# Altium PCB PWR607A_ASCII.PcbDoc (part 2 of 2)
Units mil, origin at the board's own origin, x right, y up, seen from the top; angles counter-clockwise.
Board outline 5200 x 2850 mil, 4 copper layers (Top Layer, MidLayer1, MidLayer2, Bottom Layer), stack 61.6 mil thick; 153 components, 65 nets, 324 pads, 227 vias.
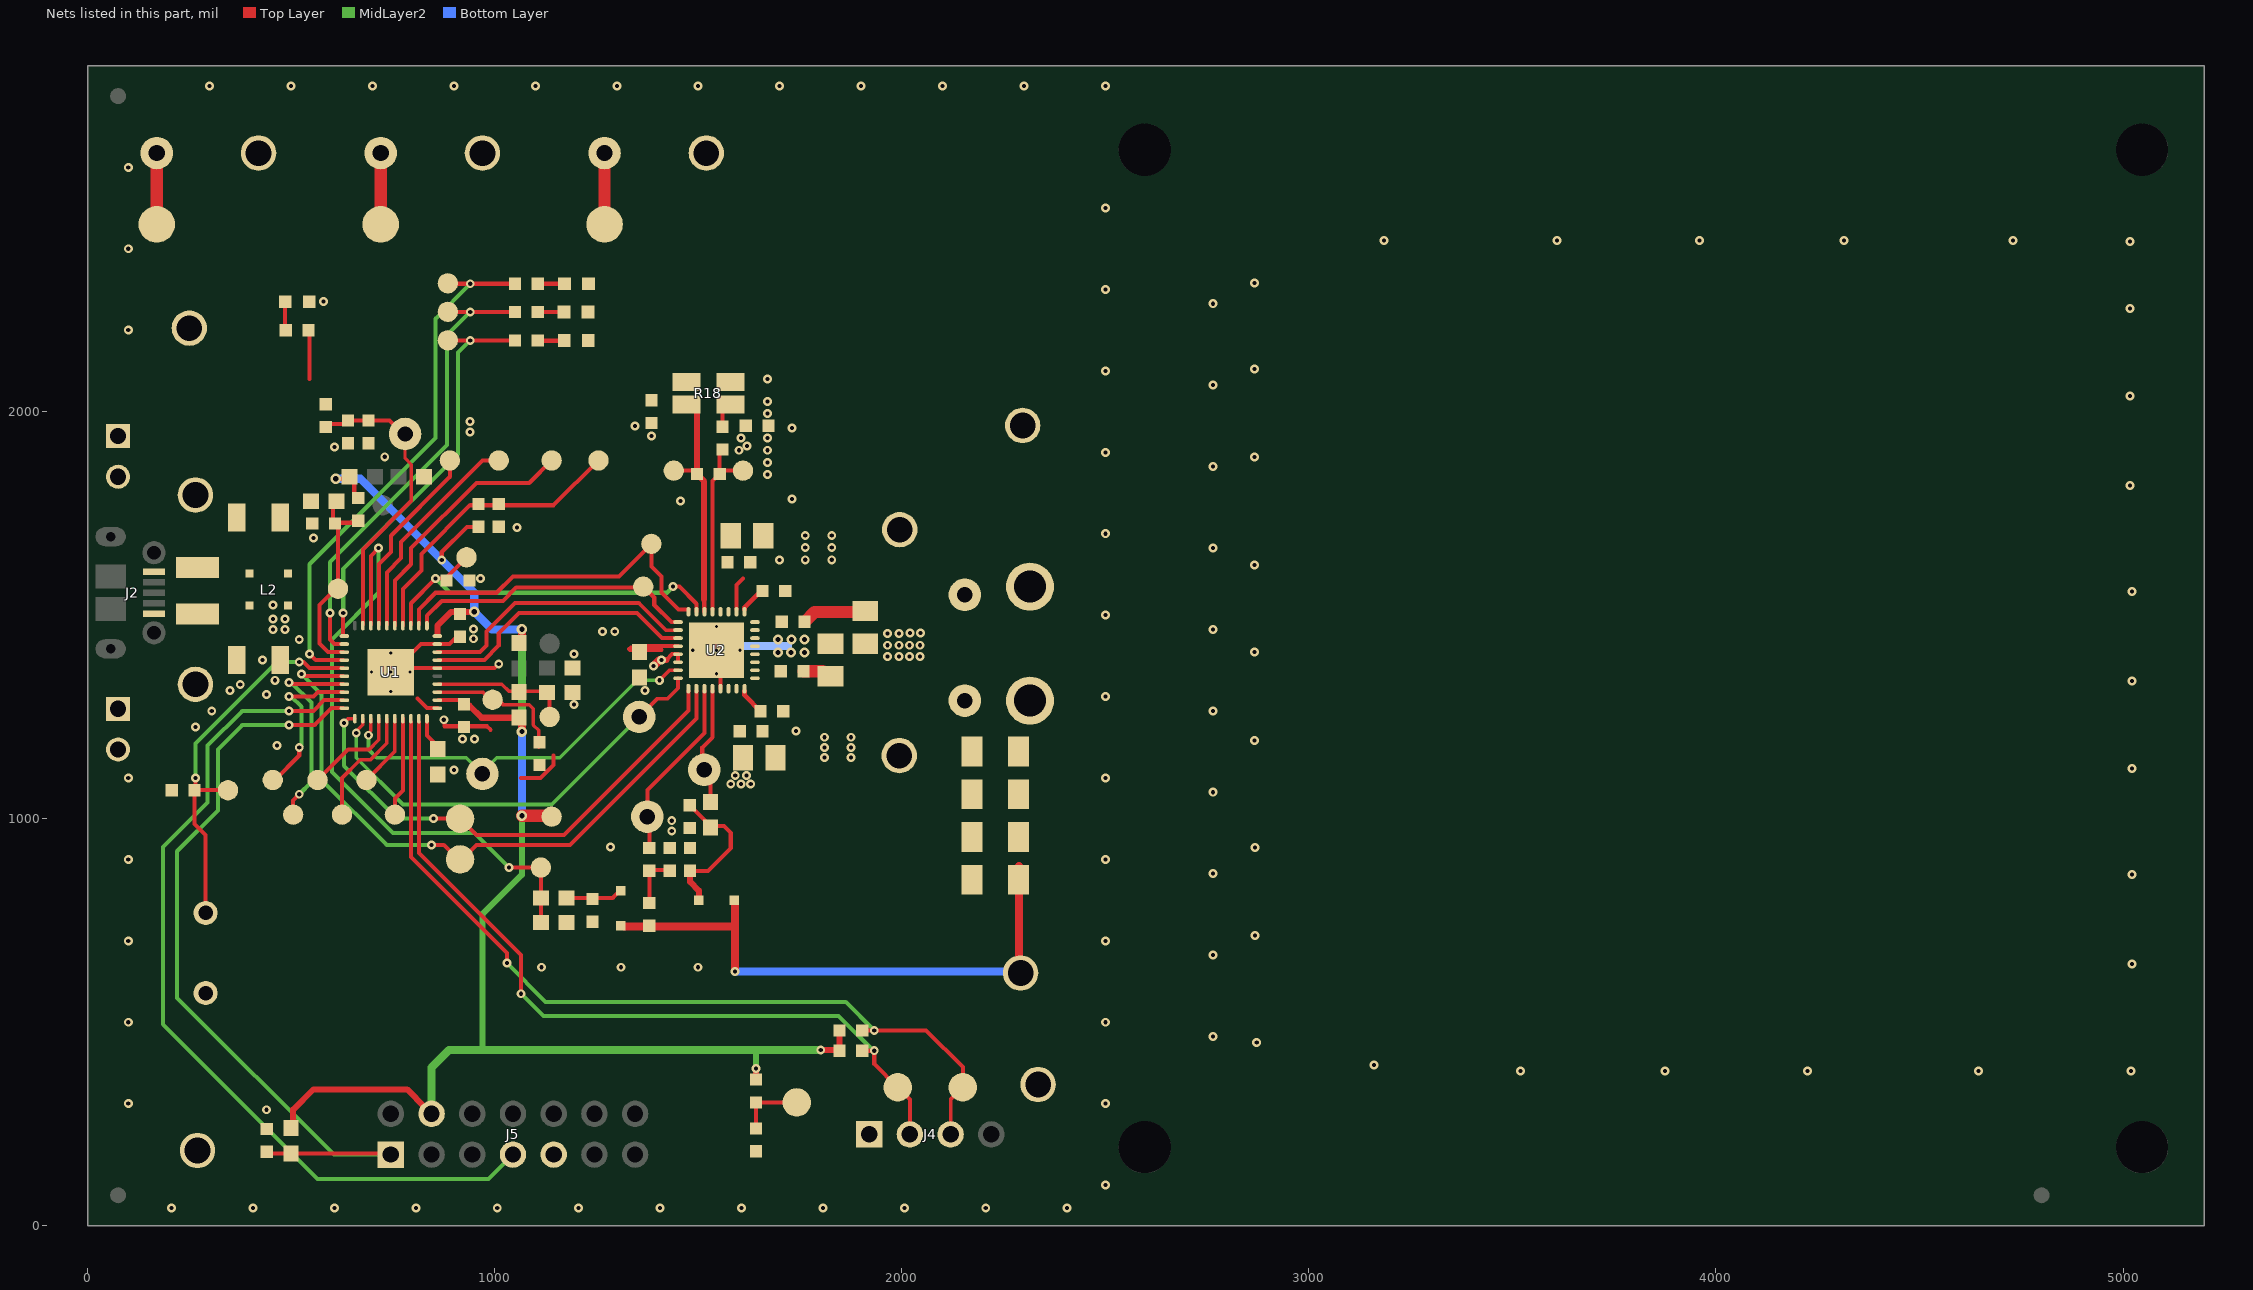
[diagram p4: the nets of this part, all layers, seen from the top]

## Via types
v1: diameter 22, hole 10, Top Layer to Bottom Layer, tented both sides, 206 vias
v2: diameter 19.68, hole 7.87, Top Layer to Bottom Layer, 10 vias
v3: diameter 24, hole 12, Top Layer to Bottom Layer, tented both sides, 6 vias
v4: diameter 26, hole 13, Top Layer to Bottom Layer, tented both sides, 5 vias

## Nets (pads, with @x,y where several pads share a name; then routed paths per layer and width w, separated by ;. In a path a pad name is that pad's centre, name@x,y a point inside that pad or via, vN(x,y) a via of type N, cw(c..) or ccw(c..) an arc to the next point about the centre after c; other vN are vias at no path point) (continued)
GND: BUZ1.2 C1.1 C2.1 C13.2 C15.2 C21.2 C22.2 C23.1 C24.1 C25.1 C26.2 C27.1 C28.2 D1.2 D4.2 D5.2 D6.2 J4.1 J5.9 L2.4 NT1.1 NTC1.1 R2.1 R5.2 R7.1 R10.1 R14.1 R25.1 R26.1 R27.1 R28.1 R30.2 R31.2 R32.1 TP7.1 TP8.1 TP9.1 TP10.1 TP51.1 TP54.1 TP57.1 U1.31 U1.36 U1.39 U1.41 U2.5 U2.6 U2.13 U2.33 | length 1028.5
  Top Layer w10: U1.41@754.84,1364.84 745,1355 783.31,1316.69 U1.41@796.31,1316.69 ; 810,1295 833.58,1271.42 U1.31@859.17,1271.42 ; U1.36@856.97,1369.84 999.84,1369.84 v1(1010,1380) ; U1.36@856.97,1370 760,1370 818.9,1428.9 888.9,1428.9 912,1452 C22.2@920,1452 ; v1(875,1243) 877,1241 877,1227 981.5,1227 990,1218.5 ; 1065,1100 1113,1100 1145,1132 1145,1155 ; 1421.89,1390 1435.94,1404.06 U2.5@1450.41,1404.06 U2.6@1450.41,1384.37 ; v2(1544.9,1413.9) 1554.74,1404.06 U2.13@1554.74,1319.41
  Top Layer w15: v1(1410,1390) 1421.89,1390
  Top Layer w20: v1(1390,1375) 1405,1390 v1(1410,1390)
  other v1: 206.33,44 406.33,44 606.33,44 806.33,44 1006.33,44 1206.33,44 1406.33,44 1606.33,44 1806.33,44 2006.33,44 2206.33,44 2406.33,44 2500,100 440,285 100,300 2500,300 3520,380 3875,380 4225,380 4645,380 5020,380 3160,395 2872,450 2765,465 100,500 2500,500 1115,635 1310,635 1500,635 5022,643 2765,665 100,700 2500,700 2868,713 5022,863 2765,865 100,900 2500,900 2868,929 1285,930 1435,970 1435,995 2765,1065 100,1100 2500,1100 900,1120 5022,1123 465,1180 2867,1192 921,1196 951,1196 265,1225 305,1265 2765,1265 1195,1280 2500,1300 440,1305 350,1315 1369,1315 375,1330 5022,1338 460,1340 430,1390 1195,1405 2867,1409 520,1440 948,1442 1265,1460 1295,1460 455,1465 485,1465 2765,1465 948,1466 455,1490 485,1490 2500,1500 455,1525 5022,1558 965,1590 2867,1623 2765,1665 555,1690 2500,1700 1055,1715 1456,1780 5017,1818 2765,1865 2867,1888 730,1889 2500,1900 1600,1905 607,1913 1620,1915 1605,1935 1385,1940 939,1950 1345,1965 939,1976 5017,2038 2765,2065 2500,2100 2867,2105 100,2200 5017,2253 2765,2265 580,2270 2500,2300 2867,2316 100,2400 5017,2418 3185,2420 3610,2420 3960,2420 4315,2420 4730,2420 2500,2500 100,2600 300,2800 500,2800 700,2800 900,2800 1100,2800 1300,2800 1500,2800 1700,2800 1900,2800 2100,2800 2300,2800 2500,2800
  other v2: 745,1312.76 1544.9,1355.83 697.76,1360 745,1360 792.24,1360 745,1407.24 1486.83,1413.9 1602.97,1413.9 1544.9,1471.97
JTAG_CLK: J5.7 U1.19 | length 2168.8
  Top Layer w10: v1@495,1270 500,1265 555,1265 581.1,1291.1 U1.19@627.87,1291.1
  MidLayer2 w10: v1(495,1265) 380,1265 295,1180 295,1040 185,930 185,495 565,115 985,115 J5.7@1045,175 J5.7@1045,190
JTAG_DATA: C26.1 J5.1 R15.1 U1.20 | length 1995
  Top Layer w10: C26.1@438,177.5 R15.1@500,177.5 ; v1(495,1230) 558,1230 599.42,1271.42 U1.20@627.87,1271.42 ; R15.1@505,177.5 J5.1@742.5,177.5 ; J5.1@742.5,192.5 J5.1@745,190
  MidLayer2 w10: v1(495,1230) 380,1230 320,1170 320,1020 220,920 220,560 605,175 730,175 J5.1@745,190
"LED MODE": R21.1 R25.2 TP27.1 U1.34 | length 358.1
  Top Layer w9: U1.34@862.13,1330.47 1017.53,1330.47 1035,1313 R25.2@1135,1313
  Top Layer w10: TP27.1@1135,1235 R25.2@1135,1313
NetBUZ1_1: BUZ1.1 R28.2 TP23.1 U1.15 | length 967.6
  Top Layer w10: v1(265,1100) 265,1072 R28.2@263,1070 ; BUZ1.1@290,768.43 290,960 263,987 R28.2@263,1070 ; TP23.1@345,1070 R28.2@263,1070 ; v1@515,1385 530,1385 545.16,1369.84 U1.15@627.87,1369.84
  MidLayer2 w10: v1(265,1100) 265,1185 465,1385 v1(520,1385)
NetC2_2: C2.2 C4.1 C5.2 C6.1 C7.2 R18.2 U2.14 U2.15 U2.27 U2.28
  other v1: 1580,1085 1605,1085 1629,1085 1591,1106 1619,1106 1730,1785 1670,1845 1670,1875 1670,1905 1670,1935 1730,1960 1670,1995 1670,2025 1670,2080
NetC3_1: C3.1 R18.3 TP1.1 U2.30 | length 586.3
  Top Layer w10: TP1.1@1440,1855 1496,1855 1496,1848 C3.1@1497,1847 ; 1514.35,1538 1515.37,1536.98
  Top Layer w11: U2.30@1515.37,1508.39 1515.37,1536.98
  Top Layer w15: C3.1@1493,1850 1514.35,1828.65 1514.35,1538 ; C3.1@1497,1847 R18.3@1497,2018
NetC3_2: C3.2 R11.1 TP2.1 U2.29 | length 463.1
  Top Layer w10: U2.29@1535.05,1514.05 1535,1828.99 C3.2@1553,1847 ; R11.1@1557,1904 1552,1904 1552,1848 C3.2@1553,1847 ; TP2.1@1610,1855 1561,1855 C3.2@1553,1847
NetC8_1: C8.1 J1.1 J1.2 J2.1 L2.2 R3.1 TP3.1
NetC8_2: C8.2 J2.5 J3.1 J3.2 L2.3 R5.1 TP4.1
NetC9_1: C9.1 R6.1 R7.2 | length 139
  Top Layer w10: C9.1@1375,873.5 C9.1@1380,873.5 ; R6.1@1380,793 C9.1@1380,872 C9.1@1380,873.5 ; C9.1@1380,877 C9.1@1380,873.5 ; R7.2@1430,873.5 C9.1@1380,873.5
NetC9_2: C9.2 TP5.1 U2.11 | length 446.6
  Top Layer w10: C9.2@1380,928 1380,1000 TP5.1@1375,1005 1375,1070 1515.9,1210.9 1515.9,1313.4 U2.11@1515.35,1313.95
NetC10_1: C10.1 C11.2 L1.1 TP6.1 U2.23 U2.24 U2.26 | length 82.5
  Top Layer w10: U2.26@1594.15,1514.05 1594.15,1574.15 1610,1590
NetC10_2: C10.2 R8.2 | length 157.9
  Top Layer w30: C10.2@1762,1484 1786,1508 R8.2@1910,1508
NetC11_1: C11.1 U2.25 | length 64.4
  Top Layer w11.5: U2.25@1613.85,1514.05 1613.85,1518.85 C11.1@1656,1561
NetC12_1: C12.1 C15.1 D3.1 R10.2 | length 378.4
  Top Layer w10: C15.1@1480,872 1524,872 1580,928 1580,965 1563,982 1530,982 1480,1032 R10.2@1480,1038 ; C15.1@1480,873.5 C15.1@1480,877
  Top Layer w15: C15.1@1480,872 1480,845 1501.69,823.31 D3.1@1501.69,800
NetC12_2: C12.2 TP12.1 U2.12 | length 311.7
  Top Layer w10: TP12.1@1505,1150 1505,1140 TP12.1@1510,1145 ; C12.2@1530,1038 1530,1085 1510,1105 TP12.1@1510,1145 ; U2.12@1535.05,1313.95 1535,1313.9 1535,1200 1510,1175 TP12.1@1510,1145
NetC13_1: C13.1 D2.1 R1.2 | length 143.8
  Top Layer w10: R1.2@1175,816.5 1186.5,805 1290,805 D2.1@1307,822
NetC14_2: C14.2 C16.2 C17.2 C18.1 C19.2 C20.1 TP14.1 U2.17 U2.18 U2.19
NetC18_2: C18.2 R16.2 | length 60.1
  Top Layer w30: C18.2@1759,1362 1805,1362 R16.2@1815,1352
NetC20_2: C20.2 U2.16 | length 69
  Top Layer w11.5: U2.16@1613.85,1313.95 1613.85,1303.15 C20.2@1655,1262
NetC23_2: C23.2 TP20.1 U1.3 U2.31 | length 915.4
  Top Layer w10: U1.3@794.21,1477.13 794.21,1529.21 v1(855,1590) 882,1590 882,1592 TP20.1@917.5,1627.5 ; v1(1438,1570) 1454,1570 1496,1528 U2.31@1496,1509
  MidLayer2 w10: v1(855,1590) 890,1555 1423,1555 v1(1438,1570)
NetC25_2: C25.2 U1.30 | length 77.3
  Top Layer w10: U1.30@833.58,1237.87 833.58,1204.42 860,1178 C25.2@860,1171.5
NetD1_1: D1.1 R4.1 | length 70.6
  Top Layer w10: D1.1@485.47,2270 485.47,2201.53 R4.1@487,2200
NetD4_1: D4.1 R17.1 | length 65.5
  Top Layer w10: R17.1@1106,2314 D4.1@1171.47,2314
NetD5_1: D5.1 R9.1 | length 55.5
  Top Layer w10: R9.1@1106,2245 D5.1@1161.47,2245
NetD6_1: D6.1 R19.1 | length 54.9
  Top Layer w10: R19.1@1106,2175 1107,2174 D6.1@1160.47,2174
NetR9_2: R9.2 TP24.1 U1.12 | length 1141.2
  Top Layer w10: v1@595,1500 595,1440 606.1,1428.9 U1.12@627.87,1428.9 ; TP24.1@885,2243 887,2245 v1(940,2245) ; v1@935,2245 v1(940,2245) ; R9.2@1040,2245 v1(940,2245)
  MidLayer2 w10: v1(595,1505) 595,1630 883,1918 883,2188 v1(940,2245)
NetR11_2: R11.2 R18.4 | length 62.4
  Top Layer w10: R11.2@1560,1963 1560,1998.31 R18.4@1579.13,2017.44
NetR17_2: R17.2 TP26.1 U1.14 | length 1333.4
  Top Layer w10: v1@540,1405 v1(545,1405) 560.47,1389.53 U1.14@627.87,1389.53 ; TP26.1@885,2315 886,2314 v1(940,2314) R17.2@1050,2314
  MidLayer2 w10: v1@540,1405 545,1410 545,1625 855,1935 855,2228 v1@940,2313
NetR19_2: R19.2 TP25.1 U1.11 | length 1018.1
  Top Layer w10: v1@625,1500 627.87,1497.13 U1.11@627.87,1448.58 ; TP25.1@885,2175 v1(940,2175) R19.2@1050,2175
  MidLayer2 w10: v1@625,1505 628,1508 628,1613.17 910,1895.17 910,2145 v1(940,2175)
  other v1: 628,1505
NetR29_2: R29.2 R32.2 TP33.1 U1.4 | length 736.2
  Top Layer w10: U1.4@774.53,1474.17 774.53,1564.53 820,1610 820,1650 940,1770 R32.2@1020,1770 ; R32.2@1010,1773 1013,1770 1145,1770 TP33.1@1255,1880
NetR30_1: R30.1 TP32.1 U1.33 | length 339.6
  Top Layer w8: 1020,1280 1085,1280 1095,1270 1095,1230 1108,1217 R30.1@1108,1175
  Top Layer w9: U1.33@859.17,1310.79 971.21,1310.79 TP32.1@984,1298
  Top Layer w10: TP32.1@995,1292 1003,1292 1010,1285 1015,1285 1020,1280
NetR31_1: R31.1 R33.2 TP47.1 | length 166.8
  Top Layer w9: R33.2@1640,301 R33.2@1642,303 ; R31.1@1642,239 R33.2@1642,303 ; TP47.1@1742,303 R33.2@1642,303
NetTP18_1: TP18.1 U1.1 U2.1 | length 740.3
  Top Layer w10: U1.1@833.58,1477.13 833.58,1498.58 870,1535 1020,1535 1053,1568 TP18.1@1383,1568 ; TP18.1@1365,1570 1392,1543 1392,1525 1434.2,1482.8 U2.1@1450,1482.8 ; TP18.1@1380,1571 TP18.1@1380,1580
NetTP19_1: TP19.1 U1.2 U2.32 | length 887.3
  Top Layer w10: U1.2@813.9,1477.13 813.9,1513.9 855,1555 1005,1555 1045,1595 1305,1595 TP19.1@1385,1675 1385,1620 1410,1595 1410,1556 1451.95,1514.05 U2.32@1475.95,1514.05
NetTP21_1: TP21.1 U1.22 U2.8 | length 1083.4
  Top Layer w9: v1(660,1210) 660,1214.54 676.1,1230.64 U1.22@676.1,1245.83 ; TP21.1@1355,1250 1400,1295 1425,1295 1450.41,1320.41 U2.8@1450.41,1345
  MidLayer2 w9: v1(660,1210) 660,1150 775,1035 1140,1035 TP21.1@1355,1250
NetTP22_1: TP22.1 U1.23 U2.7 | length 971.9
  Top Layer w9: v1(690,1205) 690,1210 695.79,1215.79 U1.23@695.79,1245.83 ; v1(1405,1340) 1429.69,1364.69 U2.7@1450.41,1364.69
  MidLayer2 w9: v1(690,1205) 690,1170 710,1150 930,1150 TP22.1@970,1110 970,1115 1005,1150 1160,1150 1350,1340 v1(1405,1340)
NetTP34_1: TP34.1 U1.5 | length 641.5
  Top Layer w10: U1.5@754.84,1474.17 754.84,1584.84 795,1625 795,1665 955,1825 1085,1825 TP34.1@1140,1880
NetTP35_1: TP35.1 U1.7 | length 472.2
  Top Layer w10: U1.7@715.47,1477.13 715.47,1625.47 745,1655 745,1695 890,1840 890,1870 TP35.1@895,1875
NetTP36_1: TP36.1 U1.25 | length 296.1
  Top Layer w9: 625,1100 670,1145 695,1145 735.16,1185.16 U1.25@735.16,1245.83
  Top Layer w10: TP36.1@625,1010 625,1100
NetTP37_1: TP37.1 U1.27 | length 243.9
  Top Layer w10: TP37.1@755,1010 755,1050 774.53,1069.53 U1.27@774.53,1245.83
NetTP38_1: TP38.1 U1.17 | length 504.1
  Top Layer w10: v1(495,1335) 499.53,1330.47 U1.17@627.87,1330.47 ; TP38.1@505,1010 505,1045 v1(520,1060)
  MidLayer2 w10: v1(495,1335) 500,1335 550,1285 550,1090 v1(520,1060)
NetTP39_1: TP39.1 U1.6 | length 545.1
  Top Layer w10: U1.6@735.16,1477.13 735.16,1605.16 770,1640 770,1680 970,1880 TP39.1@1015,1880
NetTP40_1: TP40.1 U1.24 | length 243.5
  Top Layer w9: TP40.1@565,1095 640,1170 691.88,1170 715.47,1193.59 U1.24@715.47,1245.83
NetTP41_1: TP41.1 U1.26 | length 193.9
  Top Layer w9: TP41.1@685,1095 754.84,1164.84 U1.26@754.84,1245.83
  Top Layer w10: TP41.1@675,1105 TP41.1@685,1115
NetTP42_1: TP42.1 U1.18 | length 382.6
  Top Layer w10: TP42.1@455,1095 460,1095 520,1155 v1(520,1175) ; v1(495,1300) 555,1300 565.79,1310.79 U1.18@627.87,1310.79
  MidLayer2 w10: v1(495,1300) 500,1300 525,1275 v1@525,1180
NetTP43_1: TP43.1 U1.21 U2.9 | length 1227
  Top Layer w9: v1(630,1235) 640.83,1245.83 U1.21@656.42,1245.83
  Top Layer w10: v1(850,1000) TP43.1@915,1000 955,960 1170,960 1475.95,1265.95 U2.9@1475.95,1313.95
  MidLayer2 w10: v1(630,1235) 630,1130 760,1000 v1(850,1000)
NetTP44_1: TP44.1 U1.16 U2.10 | length 1594.3
  Top Layer w10: v1(525,1355) 530,1355 534.84,1350.16 U1.16@627.87,1350.16 ; v1(845,935) 875,935 905,905 925,905 955,935 1185,935 1495.65,1245.65 U2.10@1495.65,1313.95
  MidLayer2 w10: v1(525,1355) 575,1305 575,1095 735,935 v1(845,935)
NetTP49_1: TP49.1 TP50.1 | length 175
  Top Layer w30: TP50.1@170,2460 TP49.1@170,2635
NetTP52_1: TP52.1 TP53.1 | length 175
  Top Layer w30: TP53.1@720,2460 TP52.1@720,2635
NetTP55_1: TP55.1 TP56.1 | length 175
  Top Layer w30: TP56.1@1270,2460 TP55.1@1270,2635
NetU1_37: U1.37 U2.3 | length 673.7
  Top Layer w10: U1.37@862.13,1389.53 974.53,1389.53 1010,1425 1010,1455 1060,1505 1350,1505 1411.5,1443.5 U2.3@1444.9,1443.5
NetU1_38: U1.38 U2.2 | length 689.5
  Top Layer w9: 1354,1530 1420.89,1463.11 U2.2@1450.41,1463.11
  Top Layer w10: U1.38@859.17,1409.21 964.21,1409.21 980,1425 980,1460 1050,1530 1354,1530
PEAK: R1.1 R2.2 TP13.1 U1.8 | length 1529.3
  Top Layer w10: U1.8@695.79,1477.13 695.79,1645.79 v1(715,1665) ; v1(1035,880) TP13.1@1113.5,880 R2.2@1113.5,755
  MidLayer2 w10: v1(715,1665) 715,1555 600,1440 600,1115 750,965 950,965 v1(1035,880)
PGND: C4.2 C5.1 C6.2 C7.1 NT1.2 R8.1 R16.1 TP11.1 TP17.1 U2.20 U2.21 U2.22
  other v1: 1810,1150 1875,1150 1810,1175 1875,1175 1810,1200 1875,1200 1740,1215 1965,1398 1993,1398 2019,1398 2045,1398 1965,1426 1993,1426 2019,1426 2045,1426 1965,1455 1993,1455 2020,1456 2046,1456 1700,1635 1763,1636 1828,1636 1763,1666 1828,1666 1763,1696 1828,1696
  other v3: 1696,1408 1728,1408 1761,1408 1696,1440 1729,1440 1761,1440
SCL: J4.2 R24.1 TP46.1 U1.29 | length 1973
  Top Layer w10: U1.29@813.9,1237.87 813.9,916.1 1065,665 v1(1065,570) ; R24.1@1903,430 v1(1932.5,430) 1932.5,397.5 TP46.1@1990,340 2020,310 J4.2@2020,224.41 J4.2@2017.5,226.91
  MidLayer2 w10: v1(1065,570) 1120,515 1845,515 1928.75,431.25 v1@1933.75,431.25
SDA: J4.3 R12.1 TP45.1 U1.28 | length 2121.9
  Top Layer w9: J4.3@2120,224.41 2120,310 TP45.1@2150,340
  Top Layer w10: U1.28@794.21,1237.87 794.21,905.79 1030,670 v1(1030,645) ; R12.1@1903,480 v1(1932.5,480) 2060,480 2150,390 TP45.1@2150,340
  MidLayer2 w10: v1(1030,645) 1125,550 1862.5,550 v1@1931.25,481.25
TANK: C14.1 C16.1 C17.1 C19.1 D2.2 D3.2 L1.2 R6.2 TP16.1 | length 1393.3
  Top Layer w20: D2.2@1318.69,735 1590,735 ; v1(1590,625) 1590,735 ; D3.2@1590,795 1590,735 ; TP16.1@2288.09,597 C19.1@2288.09,884
  Bottom Layer w20: v1(1590,625) TP16.1@2255,625
TSENSE: C27.2 NTC1.2 R20.2 TP28.1 U1.13 | length 481.7
  Top Layer w10: C27.2@603,1725 605,1727 603,1729 NTC1.2@603,1780 ; U1.13@627.87,1409.21 590.79,1409.21 570,1430 570,1525 605,1560 610,1560 TP28.1@615,1565 615,1727 R20.2@655,1727
VCC_3: C21.1 C22.1 C24.2 J5.4 R12.2 R15.2 R20.1 R21.2 R22.2 R23.2 R24.2 R29.1 R33.1 TP15.1 U1.32 U1.40 U2.4 | length 4310.5
  Top Layer w10: v4(610,1835) 643.5,1835 R22.2@647,1835 ; R20.1@655,1783 R22.2@655,1828 ; U1.32@862.13,1291.1 916.9,1291.1 C24.2@925,1278 ; v1(870,1635) 870,1655 932,1717 R29.1@960,1717 ; 1330,1417 1332,1415 1410,1415 ; 1335,1420 C21.1@1340,1420 ; C21.1@1368.8,1423.8 1415,1423.8 ; U2.4@1444.9,1423.8 1415,1423.8 ; U2.4@1450.41,1423.74 1415.06,1423.74 1415,1423.8
  Top Layer w15: R15.2@505,255.5 505,285 555,335 785,335 830,290 J5.4@845,290 ; U1.40@860,1452 860,1475 893,1508 v4(950,1508) ; C24.2@925,1278 938,1278 968,1248 R21.2@1067,1248 ; TP15.1@1139,1014 1149,1014 1140,1023 TP15.1@1140,1005 ; R33.1@1642,359 v1(1642,386) ; v1(1801,432) 1845,432 R24.2@1847,430 R12.2@1847,480
  Top Layer w20: v4(1067,1214) R21.2@1067,1248 ; R23.2@1067,1430 v4(1067,1465)
  Top Layer w30: v4(1067,1007) 1138,1007 TP15.1@1140,1005
  MidLayer2 w15: 970,432 970,765 1067,862 v4(1067,1007) ; v1(1642,386) 1642,430
  MidLayer2 w20: J5.4@845,290 845,389 888,432 970,432 v1(1801,432) ; v4(1067,1214) v4(1067,1465)
  Bottom Layer w20: v4(610,1835) 670,1835 v1(870,1635) 950,1555 v4(950,1508) ; v4@950.18,1508 v4(950,1508) ; v4(1067,1007) v4(1067,1214) ; v4(1067,1465) 993,1465 v4(950,1508)
VCC_5: C1.2 L2.1 R3.2 R4.2 R13.2 R18.1 | length 115
  Top Layer w10: 545,2080 R4.2@545,2195
VSENSE: C28.1 R13.1 R14.2 TP31.1 U1.9 | length 738.6
  Top Layer w8: TP31.1@780,1945 780,1885 795,1870 795,1780
  Top Layer w10: R13.1@595,1967 598,1970 637,1970 645,1978 C28.1@690,1978 742,1978 770,1950 780,1950 TP31.1@785,1945 ; U1.9@676.1,1477.13 676.1,1661.1 795,1780
  MidLayer2 w10: TP31.1@780,1940 TP31.1@785,1945
pads on no net: FID1.1 FID2.1 FID3.1 H3.0 H6.0 H9.0 H12.0 H17.0 H20.0 J2.2 J2.3 J2.4 J2.6 J2.7 J2.8 J2.9 J2.10 J2.11 J4.4 J5.2 J5.3 J5.5 J5.6 J5.8 J5.10 J5.11 J5.12 J5.13 J5.14

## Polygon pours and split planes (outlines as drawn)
NetC8_2 on Top Layer "Top Layer-No Net 14" (solid, remove dead copper, pour order 95): 200,1512 235,1545 429.7,1544.99 430,1445 390,1405 390,1355 355,1355 125,1125 30,1125 30,1355 55,1380 90,1380 110,1400 110,1495 127,1512
NetC8_1 on Top Layer "Top Layer-No Net 13" (solid, remove dead copper, pour order 96): 127,1598 105,1620 105,1710 85,1730 55,1730 30,1755 30,1985 185,1985 330,1840 330,1775 390,1775 390,1715 430,1675 430,1580 220,1580 202,1598
VCC_5 on Top Layer "Top Layer-No Net 6" (solid, remove dead copper, pour order 97): 415,1730 415,2005 525,2115 1505,2115 1505,2005 575,2005 520,1950 520,1580 460,1580 460,1685
NetC2_2 on Top Layer "Top Layer-No Net 9" (solid, remove dead copper, pour order 93): 1545,2050 1625,2050 1640,2035 1640,1820 1550,1820 1550,1505 1580,1505 1580,1605 1595,1620 1595,1655 1610,1670 1610,1725 1630,1745 1795,1745 1810,1760 1810,2035 1730,2115 1545,2115
PGND on Top Layer "Top Layer-No Net 1" (solid, remove dead copper, pour order 84): 1635,1725 1855,1725 1855,1622.5 1849.86,1615 1634,1615
NetC14_2 on Top Layer "Top Layer-No Net" (solid, remove dead copper, pour order 90): 1625,1343.95 1672,1296.95 1672,1240 1709.8,1240 1710,1240.2 2215,1240.2 2215,1306 2170,1350 2165,1355 1860,1355 1735,1345 1720,1360 1720,1380 1665,1380 1655,1390 1625,1390
NetC14_2 on Top Layer "Top Layer-No Net 2" (solid, remove dead copper, pour order 94): 1625,1293.17 1635.04,1283.54 1650.16,1269.05 1680.7,1269.05 1680.7,1230.41 2114.19,1230.41 2154.51,1191.77 2154.51,815 2215,815 2215,1293.21 2150,1355 1865,1355 1625,1346
NetC10_1 on Top Layer "Top Layer-No Net 5" (solid, remove dead copper, pour order 82): 1626,1459 1626,1534 1627,1535 1735,1535 1740,1515 1720,1495 1720,1460 1625,1460 1625,1462
VCC_3 on Top Layer "Top Layer-No Net 11" (solid, remove dead copper, pour order 89): 1275,1430 1230,1385 1230,1180 1055,1005 1055,990 1165,990 1300,1125 1300,1180 1300,1340 1350,1390 1375,1390 1395,1410 1405,1410 1498,1412.16 1498,1429
PGND on Top Layer "Top Layer-No Net 3" (solid, remove dead copper, pour order 85): 1665,1120 1905,1120 1905,1230 1645,1230 1645,1200 1665,1180
NetC2_2 on Top Layer "Top Layer-No Net 7" (solid, remove dead copper, pour order 83): 1640,1180 1620,1200 1620,1334 1570,1334 1570,1070 1640,1070
GND on Top Layer "Top Layer-No Net 8" (solid, remove dead copper, pour order 86): 657,1428.73 657,1270.87 657.1,1270.78 657.1,1270 835,1270 835,1325.86 835,1450 684.47,1450 657.1,1450 657,1449.9 657,1428.73 657,1423.72 657.1,1423.62
GND on Top Layer "Top-AGND 1" (solid, remove dead copper, pour order 98): 2598,2499 2598,1456.5 2485.5,1456.5 2485.5,1339 2598,1339 2598,314 5125.5,314 5125.5,2499
NetC10_1 on Top Layer "Top Layer-No Net 4" (solid, remove dead copper, pour order 87): 1590,1600 1595,1605 1955,1605 1955,1541.3 1938.15,1514 1590,1514
TANK on Top Layer "Top Layer-No Net 1" (solid, remove dead copper, pour order 92): 2245,815 2380,815 2380,1350 2245,1350
NetC10_1 on Top Layer "Top Layer-No Net 10" (solid, remove dead copper, pour order 91): 1937.5,1528.5 1937.5,1508.4 1950,1496.85 1955,1495 2380.29,1495 2380.29,1645 1865,1645 1865,1595 1935,1575 1937,1508.86 1938,1507.93
PGND on Top Layer "Top Layer-No Net 1" (solid, remove dead copper, pour order 88): 1930,1455 1955,1480 2070,1480 2070,1370 1954,1370 1935,1388.63 1630,1390 1630,1455
GND on Top Layer "Top Layer-No Net 12" (solid, remove dead copper, pour order 99): -1,2850 0,2849 2561,2849 2561,-1 2558,2 -2,2 -2,2844 4,2850 5,2849 7,2849
NetC2_2 on MidLayer2 "Top Layer-No Net 1" (solid, remove dead copper, pour order 101): 1730,2100 1640,2100 1640,1900 1620,1880 1620,1195 1570,1145 1570,1070 1650,1070 1650,1125 1670,1145 1670,1700 1745,1775 1745,2085
PGND on MidLayer2 "MidLayer2-No Net" (solid, remove dead copper, pour order 102): 1680,1680 1755,1755 2050,1755 2050,1655 2000,1655 1952.5,1607.5 1952.5,1537.5 2015,1475 2070,1475 2070,1110 1820,1110 1680,1250
GND on Bottom Layer "Bottom Layer-No Net" (solid, remove dead copper, pour order 105): 1,2846 5,2850 2563,2850 2563,0 2560,-3 0,-3 6,3 6,2850 18,2850
PGND on Bottom Layer "MidLayer2-No Net" (solid, remove dead copper, pour order 103): 1680,1680 1755,1755 2050,1755 2050,1655 2000,1655 1952.5,1607.5 1952.5,1537.5 2015,1475 2070,1475 2070,1110 1820,1110 1680,1250
GND on Bottom Layer "Bottom-AGND 1" (solid, remove dead copper, pour order 104): 2598.25,2499 2598.25,314 5125.75,314 5125.75,2499
GND on MidLayer1 "MidLayer1-No Net" (solid, remove dead copper, pour order 100): -1,2846 2562,2846 2562,-2 1,-2 0,-1 0,2846 6,2846

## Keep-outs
Keep-Out Layer:
  lines w8: -4,0 ccw(c0,0) 0,-4 ; -4,0 ccw(c0,0) 0,-4 ; -4,0 -4,2850 ; -4,2850 cw(c0,2850) 0,2854 ; -4,2850 cw(c0,2850) 0,2854 ; 0,-4 5200,-4 ; 0,2854 5200,2854 ; 5200,-4 ccw(c5200,0) 5204,0 ; 5200,-4 ccw(c5200,0) 5204,0 ; 5200,2854 cw(c5200,2850) 5204,2850 ; 5200,2854 cw(c5200,2850) 5204,2850 ; 5204,0 5204,2850
  text ".Layer_Name" at 577,-858.49 h60

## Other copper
Top Layer:
  rectangle net NetC14_2: 1625,1345 1655,1390
  rectangle net GND: 849,1210 898,1275
  rectangle net NetC14_2: 2073,815 2215,1248
  rectangle net GND: 885,1425 959.61,1475
  rectangle net GND: 1407,1382 1450.41,1401
  text ".Layer_Name" at 577,-858.49 h60
MidLayer1:
  text ".Layer_Name" at 577,-858.49 h60
MidLayer2:
  text ".Layer_Name" at 577,-858.49 h60
Bottom Layer:
  rectangle net GND: 1595,1399.13 1655,1435
  text ".Layer_Name" at 577,-858.49 h60

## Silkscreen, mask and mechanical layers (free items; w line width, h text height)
Top Overlay:
  lines w10: 25,2070 285,2070 365,1990 365,1915 365,1790
  lines w40: 2809.5,350.5 4909.5,350.5 4909.5,2450.5 2809.5,2450.5 2809.5,350.5
  text "2015" at 1605,2530 h60
  text "bq50002EVM-607" at 1668,2430 h100
  text "PWR607  Rev. A" at 1780,2346 h60
  text "V_SENSE" at 745,2005 h50
  text "+5V" at 150,1965 h80
  text "VIN" at 160,1895 h80
  text "CS+" at 1325,1797 h50
  text "CS-" at 1655,1796 h50
  text "PWM2" at 1235,1610 h50
  text "/U-D" at 1375,1610 h50
  text "I_SENSE" at 1040,1600 h50
  text "SW1" at 2015,1535 h50
  text "T_SENSE" at 650,1520 h50
  text "PWM1" at 1190,1505 h50
  text "/CLK" at 1325,1505 h50
  text "FOD_THR" at 1083,1468 h50
  text "SW2" at 2010,1275 h50
  text "LED" at 1185,1195 h50
  text "GND" at 145,1190 h80
  text "_" at 200,1170 h90
  text "DMN2" at 1430,1170 h50
  text "DMO1" at 1272,1124 h50
  text "DMO2" at 990,1025 h50
  text "DMN1" at 1204,975 h50
  text "BUZZ" at 285,965 h50
  text "BP3" at 1020,940 h50
  text "PEAK" at 1145,845 h50
  text "TANK" at 2085,585 h50
  text ".Layer_Name" at 577,-858.49 h60
Bottom Overlay:
  text ".Layer_Name" at 577,-858.49 h60
Top Paste:
  text ".Layer_Name" at 577,-858.49 h60
Bottom Paste:
  text ".Layer_Name" at 577,-858.49 h60
Top Solder:
  rectangle: 2595,310 4945,2500
  text ".Layer_Name" at 577,-858.49 h60
  text ".Layer_Name" at 577,-858.49 h60
Bottom Solder:
  text ".Layer_Name" at 577,-858.49 h60
Drill Guide:
  text ".Layer_Name" at 577,-858.49 h60
M1 Board Outline:
  the board outline again, w10
  text ".Layer_Name" at 577,-858.49 h60
M2 Board Dimensions:
  rectangle: 124.5,-410.5 499.5,-285.5
  rectangle: -0.5,-285.5 124.5,-160.5
  lines w7: -0.5,-285.5 999.5,-285.5 ; 124.5,-410.5 124.5,-160.5 ; 249.5,-410.5 249.5,-160.5 ; 499.5,-410.5 499.5,-160.5 ; 749.5,-410.5 749.5,-160.5 ; -0.5,-410.5 -0.5,-160.5 999.5,-160.5 999.5,-410.5 -0.5,-410.5
  text ".Layer_Name" at 577,-858.49 h60
M3 3D STEP Top:
  text ".Layer_Name" at 577,-858.49 h60
M4 3D STEP Bottom:
  text ".Layer_Name" at 577,-858.49 h60
M5 Assembly Top:
  lines w7: 5334,145.5 6459,145.5 ; 5334,268 6456.5,268 ; 5649,25.5 5649,388 ; 6034,25.5 5334,25.5 ; 6034,388 5334,388 ; 5334,25.5 5334,388 ; 5334,25.5 6459,25.5 6459,388 5334,388
  lines w10: -292,-930.17 6308,-930.17 ; -292,-726.83 6310,-726.83 ; -292,-523.5 -292,-1133.5 3713,-1133.5 6310,-1133.5 6310,-523.5 -291.5,-523.5 -291.5,-1133.5 1284,-1133.5 ; 2173,-1133.5 2173,-523.5 ; 3440,-726.83 3440,-523.5 ; 4280,-726.83 4280,-523.5 ; 4902,-1140 4902,-937.17
  text "TABLE 1" at 5721.5,423 h40
  text "Variant" at 5359,313 h40
  text "Label text" at 5794,313 h40
  text "001" at 5426.5,193 h40
  text "bq50002 + bq500511" at 5704,190.5 h40
  text "COMPONENTS MARKED 'DNP' SHOULD NOT BE POPULATED." at 1153.5,-318.5 h60
  text "ASSEMBLY VARIANT:" at 1153,-434 h60
  text ".VariantName" at 2189,-434 h60
  text "PCB VIEWED FROM TOP SIDE" at -228.5,-655.67 h60
  text "BOARD #:" at 2248,-655.67 h60
  text ".PRJ_Number" at 2793.5,-655.67 h60
  text "REV:" at 3638,-655.67 h60
  text ".PCB_Rev" at 3929.5,-655.67 h60
  text "SVN REV:" at 4476,-655.67 h60
  text ".VersionControl_RevNumber" at 4982,-655.67 h60
  text "IGNORE ->" at -228.5,-858.49 h60
  text "PLOT NAME =" at -228.5,-1064.34 h60
  text ".plot_File_Name" at 577,-1064.34 h60
  text "GENERATED    :" at 2250,-1064.34 h60
  text ".Print_Date" at 3119.5,-1064.34 h60
  text ".Print_Time" at 3848.5,-1064.34 h60
  text "TEXAS INSTRUMENTS" at 5113,-1064.34 h60
M6 Assembly Bottom:
  lines w10: -292.5,-727.33 6309.5,-727.33 ; -290.5,-930.67 6309.5,-930.67 ; 1115.5,-1140.5 1115.5,-937.67 ; 1737.5,-727.33 1737.5,-524 ; 2577.5,-727.33 2577.5,-524 ; 3844.5,-1134 3844.5,-524 ; 4733.5,-1134 6309,-1134 6309,-524 -292.5,-524 -292.5,-1134 2304.5,-1134 6309.5,-1134 6309.5,-524
  text "COMPONENTS MARKED 'DNP' SHOULD NOT BE POPULATED." at 6102,-318 h60
  text ".VariantName" at 5058,-434 h60
  text "ASSEMBLY VARIANT:" at 6097,-434 h60
  text ".VersionControl_RevNumber" at 1035.5,-656.17 h60
  text "SVN REV:" at 1541.5,-656.17 h60
  text ".PCB_Rev" at 2088,-656.17 h60
  text "REV:" at 2379.5,-656.17 h60
  text ".PRJ_Number" at 3224,-656.17 h60
  text "BOARD #:" at 3769.5,-656.17 h60
  text "PCB VIEWED FROM BOTTOM SIDE" at 6246,-656.17 h60
  text "IGNORE ->" at 2547.85,-858.49 h60
  text "TEXAS INSTRUMENTS" at 904.5,-1064.84 h60
  text ".Print_Time" at 2169,-1064.84 h60
  text ".Print_Date" at 2898,-1064.84 h60
  text "GENERATED    :" at 3767.5,-1064.84 h60
  text ".plot_File_Name" at 5440.5,-1064.84 h60
  text "PLOT NAME =" at 6246,-1064.84 h60
M9 Title Sheet:
  lines w10: -491.5,1041.5 -291.5,1041.5 ; -491.5,3416.5 -291.5,3416.5 ; -491.5,5791.5 -291.5,5791.5 ; 2008.5,-1333.5 2008.5,-1133.5 ; 2008.5,7966.5 2008.5,8166.5 ; 4508.5,-1333.5 4508.5,-1133.5 ; 4508.5,7966.5 4508.5,8166.5 ; 6321,-1133.5 6321,-523.5 11303.5,-523.5 ; 7008.5,-1333.5 7008.5,-1133.5 ; 7008.5,7966.5 7008.5,8166.5 ; 9508.5,-1333.5 9508.5,-1133.5 ; 9508.5,7966.5 9508.5,8166.5 ; 11303.5,-1133.5 11303.5,-523.5 ; 11303.5,-823.5 14303.5,-823.5 ; 11303.5,-223.5 14303.5,-223.5 ; 11304.5,370.5 14304.5,370.5 ; 12008.5,-1333.5 12008.5,-1133.5 ; 12008.5,7966.5 12008.5,8166.5 ; 12808.5,-1123.5 12808.5,-523.5 ; 14303.5,-523.5 11303.5,-523.5 ; 14303.5,76.5 11303.5,76.5 ; 14308.5,66.5 14308.5,-1133.5 ; 14308.5,871 11304.5,871 11303.5,871 11303.5,370.5 11303.5,76.5 ; 14308.5,1041.5 14508.5,1041.5 ; 14308.5,3416.5 14508.5,3416.5 ; 14308.5,5791.5 14508.5,5791.5 ; 11303.5,-523.5 11303.5,76.5 ; 14308.5,-1133.5 -291.5,-1133.5 -291.5,7966.5 14308.5,7966.5 14308.5,-1133.5 ; -491.5,-1333.5 14508.5,-1333.5 14508.5,8166.5 -491.5,8166.5 -491.5,-1333.5
  text "1" at 739.84,8036.5 h60
  text "2" at 3235.5,8036.5 h60
  text "3" at 5724.84,8036.5 h60
  text "4" at 8231.51,8036.5 h60
  text "5" at 10730.5,8036.5 h60
  text "6" at 13235.5,8036.5 h60
  text "A" at -416.5,6893.5 h60
  text "A" at 14383.5,6893.5 h60
  text "B" at -416.5,4513.5 h60
  text "B" at 14383.5,4513.5 h60
  text "C" at -416.5,2138.5 h60
  text "C" at 14383.5,2138.5 h60
  text "PROJECT TITLE:" at 11343.5,277.5 h60
  text ".PRJ_Title" at 11393.5,144.17 h60
  text "DESIGNED FOR:" at 11343.5,-23.5 h60
  text ".PRJ_Customer" at 11393.5,-163.5 h60
  text "D" at -416.5,-231.5 h60
  text "D" at 14383.5,-231.5 h60
  text "FILE NAME:" at 11343.5,-323.5 h60
  text ".PCB_File_Name_No_Path" at 11393.5,-443.5 h60
  text "Texas Instruments (TI) and/or its licensors do not warrant the accuracy or completeness of this specification" at 6374,-605.34 h40
  text "ENGINEER:" at 11343.5,-613.5 h60
  text "LAYOUT BY:" at 12848.5,-613.5 h60
  text "or any information contained therein. TI and/or its licensors do not warrant that this design will meet" at 6329.01,-718 h40
  text ".PRJ_Engineer" at 11393.5,-768.49 h60
  text ".PCB_Layout" at 12899,-768.49 h60
  text "the specifications, will be suitable for your application or fit for any particular purpose, or will operate in" at 6329.01,-830.67 h40
  text ".Layer_Name" at 577,-858.49 h60
  text "ALTIUM DESIGNER VERSION:" at 12848.5,-923.5 h60
  text "an implementation. TI and/or its licensors do not warrant that the design is production worthy. You should" at 6329.01,-943.33 h40
  text "completely validate and test your design implementation to confirm the system functionality for your application." at 6374,-1056 h40
  text ".print_Scale" at 11393.5,-1056.83 h60
  text ".Application_BuildNumber" at 12899,-1056.83 h60
  text "1" at 739.84,-1263.5 h60
  text "2" at 3235.5,-1263.5 h60
  text "3" at 5724.84,-1263.5 h60
  text "4" at 8231.51,-1263.5 h60
  text "5" at 10730.5,-1263.5 h60
  text "6" at 13235.5,-1263.5 h60
M10 Fab Notes:
  drawing of 212 lines, arcs and shapes, not listed
  text "DESIGN INFORMATION" at 12381.02,6810 h60
  text "(REFER ALSO ARRAY/PANEL PROFILING INFORMATION)" at 12019.46,6648.29 h60
  text "BOARD SIZE" at 11333.46,6644 h60
  text "2850MIL" at 11795.78,6516.18 h60
  text "X" at 12301.46,6516.18 h60
  text "5200MIL" at 12532.78,6516.18 h60
  text "Number of Layers :" at 11736.46,6319 h60
  text "4" at 12831.27,6309 h60
  text "MIN. TRACK WIDTH:" at 11736.46,6180 h60
  text "8" at 12832.7,6180 h60
  text "MIL" at 12987.46,6180 h60
  text "MIN. CLEARANCE:" at 11736.46,6048 h60
  text "8" at 12832.7,6048 h60
  text "MIL" at 12987.46,6048 h60
  text "MIN. VIA PAD SIZE:" at 11736.46,5916 h60
  text "20" at 12802.71,5916 h60
  text "MIL" at 12987.46,5916 h60
  text "0.15mm (6MIL)" at 12431.46,5774.29 h60
  text "MINIMUM ANNULAR RING" at 11407.23,5770 h60
  text "EXTERNAL" at 13139.46,5770 h60
  text "PER" at 11607.23,5652 h60
  text "IPC-D-275 CLASS 2 LEVEL C" at 11827.23,5652 h60
  text "MIL, HOLES" at 13315.46,5539.71 h60
  text "+/-" at 12923,5539 h60
  text "+/-" at 13777,5539 h60
  text "REGISTRATION TOLERANCES:" at 11407.23,5534 h60
  text "METAL" at 12607,5534 h60
  text "5" at 13183.2,5534 h60
  text "3" at 14016.2,5534 h60
  text "MIL" at 14132.46,5534 h60
  text "MATERIAL:" at 11332.46,5324.54 h60
  text "FR-4 High Tg" at 12318.9,5184.21 h60
  text "FR-408" at 11753.46,5175.64 h60
  text "X" at 12165.46,5175.64 h60
  text "OTHER" at 13241.46,5175.64 h60
  text "62 MIL (1.6mm) +/-10%" at 12073.56,5012.92 h60
  text "THICKNESS:" at 11407.23,5008.64 h60
  text "X" at 11945.4,5008.64 h60
  text "OTHER" at 13358.46,5008.64 h60
  text "TOLERANCE:" at 11407.23,4850.64 h60
  text "X" at 12246.53,4850.64 h60
  text "ANSI IPC-6012 TYPE 3 CLASS 2" at 12433.48,4850.64 h60
  text "OTHER +/-" at 12433.46,4694.64 h60
  text "BOW & TWIST:" at 11407.23,4537.64 h60
  text "X" at 12246.53,4537.64 h60
  text "ANSI IPC-6012 TYPE 3 CLASS 2" at 12433.48,4537.64 h60
  text "OTHER +/-" at 12433.46,4379.13 h60
  text "COPPER THICKNESS (FINISHED):" at 11332.46,4243.64 h60
  text "1.4MIL (1oz)" at 12212.46,4090.92 h60
  text "2MIL (1.4oz)" at 12979.46,4090.92 h60
  text "2.8MIL (2oz)" at 13706.46,4090.92 h60
  text "OUTER:" at 11689.46,4086.64 h60
  text "X" at 12084,4086 h60
  text "1.4MIL (1oz)" at 12212.46,3933.92 h60
  text "2.8MIL (2oz)" at 12979.46,3933.92 h60
  text "N/A" at 13706,3934.29 h60
  text "INNER SIGNAL:" at 11400.38,3929.64 h60
  text "X" at 12085.42,3929.64 h60
  text "DRILLING:" at 11332.46,3790.64 h60
  text "REFERENCE:" at 11407.23,3673.64 h60
  text "X" at 12055.46,3673.64 h60
  text "AS SHOWN" at 12242.46,3673.64 h60
  text "X" at 12956.46,3673.64 h60
  text "NC_DRILL FILES" at 13093.46,3673.64 h60
  text "PTH MIN COPPER THICKNESS:" at 11407.23,3515.64 h60
  text "X" at 12757.46,3515.64 h60
  text "1MIL" at 12894.46,3515.64 h60
  text "OTHER" at 13391.46,3515.64 h60
  text "BOARD FINISH:" at 11332.46,3356.64 h60
  text "SILKSCREEN:" at 11487.68,3238.64 h60
  text "X" at 12436.46,3238.64 h60
  text "TOP" at 12562.46,3238.64 h60
  text "BOTTOM" at 13073.46,3238.64 h60
  text "SILKSCREEN COLOR:" at 11487.68,3071.64 h60
  text "X" at 12435.42,3071.64 h60
  text "WHITE" at 12562.46,3071.64 h60
  text "OTHER" at 13073.46,3071.64 h60
  text "SOLDER RESIST COLOR:" at 11487.68,2901.64 h60
  text "X" at 12055.42,2742.44 h60
  text "GREEN" at 12182.46,2742.44 h60
  text "BLUE" at 12773.46,2742.44 h60
  text "OTHER" at 13311.46,2742.44 h60
  text "IMMERSION GOLD (ENIG)" at 12393.46,2553.92 h60
  text "ENEPIG" at 13731,2550.64 h60
  text "SURFACE FINISH:" at 11332.46,2549.64 h60
  text "X" at 12205,2545 h60
  text "IMM. TIN/SILVER OR EQUIV" at 11662,2392.64 h60
  text "OTHER" at 13093.46,2392.64 h60
  text "ARRAY/PANEL:" at 11332.46,2213.64 h60
  text "CUT AND TRIM PER MECH LAYER 1" at 12393.46,2209.35 h60
  text "N.C. ROUTE" at 12393.46,2057.64 h60
  text "X" at 13072.46,2057.64 h60
  text "V. SCORE" at 13259.46,2057.64 h60
  text "CERTIFICATION:" at 11332.46,1920.64 h60
  text "MATERIALS AND WORKMANSHIP FOR ALL PCBS" at 12057.46,1920.64 h60
  text "TO MEET OR EXCEED THE REQUIREMENTS OF:" at 12057.46,1822.64 h60
  text "X" at 11683.96,1686.13 h60
  text "ANSI IPC-A-600F CLASS ->" at 11822.96,1686.13 h60
  text "X" at 13462.02,1686.13 h60
  text "2" at 13580.96,1686.14 h60
  text "1" at 13265.96,1684.64 h60
  text "3" at 13934.96,1684.64 h60
  text "X" at 11686.02,1526.64 h60
  text "UL 94V-0" at 11822.96,1526.64 h60
  text "X" at 12498.02,1526.64 h60
  text "RoHS" at 12634.96,1526.64 h60
  text "OTHER" at 13279.36,1526.64 h60
  text "PER ORDER" at 13676.42,1526.64 h60
  text "ADDITIONAL REQUIREMENTS:" at 11332.46,1385.64 h60
  text "MICROSECTION:" at 11407.23,1270.64 h60
  text "YES" at 12312.96,1270.64 h60
  text "REQUIRED" at 13174.46,1114.49 h60
  text "BARE BOARD ELEC. TEST:" at 11407.23,1111.64 h60
  text "NONE" at 12712.96,1111.64 h60
  text "X" at 13047.46,1111.64 h60
  text "PER ORDER" at 13766.46,1111.64 h60
  text "MANUFACTURER'S UL:" at 11407.23,954.64 h60
  text "RAIL" at 12572.96,950.35 h60
  text "METAL" at 13064.77,950.35 h60
  text "X" at 13440,950 h60
  text "SILK" at 13576.46,950.35 h60
  text ".Layer_Name" at 577,-858.49 h60
M11 Gerber Information:
  lines w10: -292,-930.17 6308,-930.17 ; -292,-726.83 6310,-726.83 ; -292,-523.5 -292,-1133.5 3713,-1133.5 6310,-1133.5 6310,-523.5 -291.5,-523.5 -291.5,-1133.5 1284,-1133.5 ; 2173,-1133.5 2173,-523.5 ; 3440,-726.83 3440,-523.5 ; 4280,-726.83 4280,-523.5 ; 4902,-1140 4902,-937.17
  text "ALL ARTWORK VIEWED FROM TOP SIDE" at -228.5,-655.67 h60
  text "BOARD #:" at 2248,-655.67 h60
  text ".PRJ_Number" at 2793.5,-655.67 h60
  text "REV:" at 3638,-655.67 h60
  text ".PCB_Rev" at 3929.5,-655.67 h60
  text "SVN REV:" at 4476,-655.67 h60
  text ".VersionControl_RevNumber" at 4982,-655.67 h60
  text "LAYER NAME =" at -228.5,-858.49 h60
  text "PLOT NAME =" at -228.5,-1064.34 h60
  text ".plot_File_Name" at 577,-1064.34 h60
  text "GENERATED    :" at 2250,-1064.34 h60
  text ".Print_Date" at 3119.5,-1064.34 h60
  text ".Print_Time" at 3848.5,-1064.34 h60
  text "TEXAS INSTRUMENTS" at 5113,-1064.34 h60
M12 Stackup:
  lines w6: 11360,7693 14180,7693 ; 11360,7805.6 14180,7805.6 ; 11300,6976 ccw(c11336,6976) 11336,6940 14204,6940 ccw(c14204,6976) 14240,6976 14240,7904 ccw(c14204,7904) 14204,7940 11336,7940 ccw(c11336,7904) 11300,7904 11300,6976
  text "Layer Stack Up Detail for: PWR607A.PcbDoc" at 11360,7835 h51
  text "Layer" at 11360,7763.6 h26
  text "Gerber" at 12347.8,7763.6 h26
  text "Copper" at 12989.85,7763.6 h26
  text "Dielectric" at 13674.35,7763.6 h26
  text "Name" at 11360,7711.6 h26
  text "Document" at 12347.8,7711.6 h26
  text "Thickness" at 12989.85,7711.6 h26
  text "Material" at 13674.35,7711.6 h26
  text "Top Solder Mask" at 11360,7637.92 h36
  text "(.GTS)" at 12347.8,7637.92 h36
  text "Solder Resist" at 13674.35,7637.92 h36
  text "Top Layer" at 11360,7533.75 h36
  text "(.GTL)" at 12347.8,7533.75 h36
  text "1.4mil" at 12989.85,7533.75 h36
  text "FR-4 High Tg" at 13674.35,7481.67 h36
  text "MidLayer1" at 11360,7429.58 h36
  text "(.G1)" at 12347.8,7429.58 h36
  text "1.4mil" at 12989.85,7429.58 h36
  text "FR-4 High Tg" at 13674.35,7377.5 h36
  text "MidLayer2" at 11360,7325.42 h36
  text "(.G2)" at 12347.8,7325.42 h36
  text "1.4mil" at 12989.85,7325.42 h36
  text "FR-4 High Tg" at 13674.35,7273.33 h36
  text "Bottom Layer" at 11360,7221.25 h36
  text "(.GBL)" at 12347.8,7221.25 h36
  text "1.4mil" at 12989.85,7221.25 h36
  text "Bottom Solder Mask" at 11360,7117.08 h36
  text "(.GBS)" at 12347.8,7117.08 h36
  text "Solder Resist" at 13674.35,7117.08 h36
  text ".Layer_Name" at 577,-858.49 h60
M13 Component Bodies Top:
  text ".Layer_Name" at 577,-858.49 h60
M14 Component Bodies Bottom:
  text ".Layer_Name" at 577,-858.49 h60
M15 Courtyards Top:
  text ".Layer_Name" at 577,-858.49 h60
M16 Courtyards Bottom:
  text ".Layer_Name" at 577,-858.49 h60
Drill Drawing:
  text ".legend" at 5350,930 h60
  text "Drill Table" at 5355,720 h60
  text ".Layer_Name" at 577,-858.49 h60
